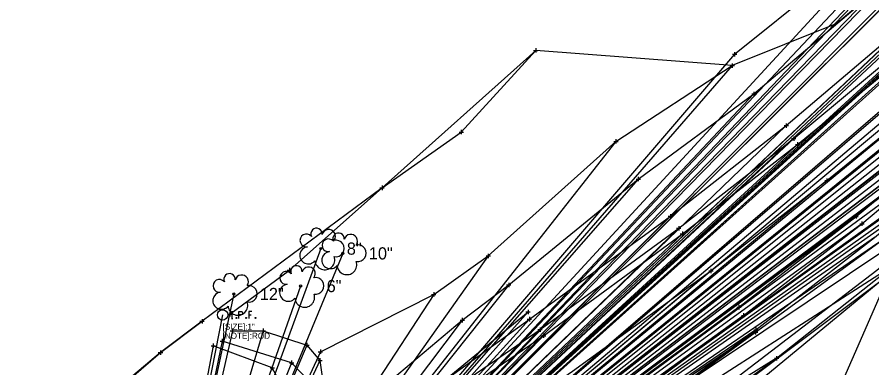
# Model space of a CAD drawing. Extents: x 2048206 to 2051708, y 354200 to 357644.
# Drawn here: x 2049529.9 to 2049726.6, y 356439.5 to 356520.1 of the extents above; entities that cross this region are included whole.
import ezdxf

# ---------------------------------------------------------------- set-up
doc = ezdxf.new("R2010")
doc.units = 0
for name, color, linetype in [('HY_X_Water_Edge', 7, 'Continuous'), ('PM_X_CL_Double_Solid', 7, 'Continuous'), ('PM_X_Edge_Line', 7, 'Continuous'), ('RD_X_GR_Lt', 7, 'Continuous'), ('RD_X_GR_Rt', 7, 'Continuous'), ('RW_X_CL_1000_Cardinal_Points', 7, 'Continuous'), ('RW_X_CL_1000_Curve_Data', 7, 'Continuous'), ('RW_X_CL_1000_Distances', 7, 'Continuous'), ('RW_X_CL_1000_Stations', 7, 'Continuous'), ('RW_X_CL_100_Bearings', 7, 'Continuous'), ('RW_X_CL_100_Distances', 7, 'Continuous'), ('RW_X_CL_500_Stations', 7, 'Continuous'), ('SC_Scratch1', 7, 'Continuous'), ('SV_X_Mon_Cells_Found_Text', 7, 'Continuous'), ('SV_X_Terrain_Boundary', 7, 'Continuous'), ('UT_X_Cable_TV', 7, 'Continuous'), ('UT_X_Telecom', 7, 'Continuous'), ('VG_X_Text', 7, 'Continuous'), ('VG_X_Tree_Line_Rt', 7, 'Continuous')]:
    doc.layers.add(name, color=color, linetype=linetype)

msp = doc.modelspace()

# ---------------------------------------------------------------- linework, layer by layer
at = {"layer": 'HY_X_Water_Edge'}
for points in [[(2049599.68, 356443.17), (2049625.75, 356456.37), (2049638.32, 356465.2), (2049667.68, 356491.55), (2049694.48, 356508.98)], [(2049579.41, 356447.98), (2049586.53, 356447.98), (2049596.56, 356444.7), (2049599.58, 356441.17), (2049601.05, 356430.45), (2049601.6, 356418.96)], [(2049598.72, 356417.71), (2049595.35, 356421.56), (2049594.87, 356427.98), (2049588.58, 356439.46), (2049575.02, 356444.56)]]:
    msp.add_lwpolyline(points, dxfattribs=at)
at = {"layer": 'PM_X_CL_Double_Solid'}
msp.add_lwpolyline([(2049375.85, 356259.2), (2049407.64, 356278.84), (2049446.04, 356302.47), (2049477.81, 356322.2), (2049514.36, 356345.05), (2049555.57, 356371.24), (2049580.57, 356387.08), (2049597.36, 356397.99), (2049622.58, 356414.43), (2049657.71, 356438.71), (2049689.55, 356461.77), (2049716.26, 356482.53), (2049748.26, 356508.44), (2049787.5, 356543.51), (2049807.89, 356562.69), (2049832.63, 356587.13)], dxfattribs=at)
at = {"layer": 'PM_X_Edge_Line'}
for points in [[(2049370.29, 356268.21), (2049401.1, 356287.18), (2049440.53, 356311.34), (2049471.49, 356330.83), (2049508.99, 356354.34), (2049549.13, 356379.71), (2049574.88, 356396.03), (2049597.51, 356410.76), (2049600.43, 356412.78), (2049602.51, 356414.08), (2049606.07, 356416.36), (2049609.95, 356418.83), (2049616.41, 356423.19), (2049651.04, 356446.85), (2049683, 356470.3), (2049709.5, 356490.86), (2049741.12, 356516.75), (2049780.37, 356551.36), (2049801.22, 356570.77), (2049825.54, 356594.9)], [(2049381.31, 356250.14), (2049413.48, 356270.07), (2049450.91, 356293.28), (2049483.11, 356313.23), (2049520.27, 356336.44), (2049560.54, 356361.97), (2049585.44, 356377.69), (2049604.83, 356390.29), (2049628.89, 356406.09), (2049663.97, 356430.06), (2049696.02, 356453.42), (2049722.97, 356474.28), (2049754.43, 356500.26), (2049794.54, 356535.57), (2049814.95, 356554.55), (2049840.5, 356579.69)]]:
    msp.add_lwpolyline(points, dxfattribs=at)
at = {"layer": 'RD_X_GR_Lt'}
msp.add_lwpolyline([(2049366.77, 356272.94), (2049397.1, 356292.33), (2049436.39, 356315.64), (2049468.85, 356335.46), (2049506.36, 356358.42), (2049546.62, 356383.24), (2049572.79, 356399.73), (2049597.57, 356415.65), (2049605.8, 356420.98), (2049614.6, 356426.92), (2049627.17, 356435.72), (2049647.48, 356452.34)], dxfattribs=at)
at = {"layer": 'RD_X_GR_Rt'}
msp.add_lwpolyline([(2049564.55, 356352.93), (2049589.5, 356371.59), (2049618.71, 356390.8), (2049633.04, 356400.3), (2049668.46, 356424.71), (2049699.93, 356448.21), (2049727.18, 356469.44), (2049758.19, 356495.07), (2049799.24, 356531.67), (2049818.56, 356549.77), (2049844.67, 356575.35)], dxfattribs=at)
at = {"layer": 'RW_X_CL_1000_Cardinal_Points'}
for p in [(2049967.48, 356704.03), (2049967.48, 356704.03), (2049887.53, 356618.37), (2049808.42, 356609.48), (2049813.35, 356606.55), (2049820.56, 356599.28), (2049794.64, 356598.37), (2049825.1, 356595.26), (2049825.54, 356594.9), (2049787.92, 356592.43), (2049832.63, 356587.13), (2049832.63, 356587.13), (2049791.16, 356584.29), (2049840.5, 356579.69), (2049841.77, 356578.41), (2049796.57, 356575.48), (2049844.65, 356575.39), (2049844.67, 356575.35), (2049799.72, 356572.07), (2049801.22, 356570.77), (2049762.44, 356568.63), (2049851.09, 356567.09), (2049768.52, 356562.93), (2049807.89, 356562.69), (2049807.89, 356562.69), (2049776.5, 356555.74), (2049814.95, 356554.55), (2049816.11, 356553.32), (2049779.27, 356552.86), (2049780.37, 356551.36), (2049839.38, 356550.87), (2049839.38, 356550.87), (2049818.68, 356550.01), (2049818.56, 356549.77), (2049787.5, 356543.51), (2049787.5, 356543.51), (2049734.41, 356543.24), (2049824.29, 356542.01), (2049794.54, 356535.57), (2049795.79, 356534.44), (2049799.24, 356531.67), (2049799.22, 356531.65), (2049732.64, 356530.57), (2049806, 356525.86), (2049738.23, 356521.78), (2049740.27, 356518.46), (2049741.12, 356516.75), (2049695.02, 356511.58), (2049694.48, 356508.98), (2049748.26, 356508.44), (2049748.26, 356508.44), (2049699.45, 356502.46), (2049754.43, 356500.26), (2049755.38, 356498.64), (2049706.89, 356495.18), (2049758.22, 356495.14), (2049758.19, 356495.07), (2049708.61, 356492.19), (2049667.68, 356491.55), (2049709.5, 356490.86), (2049762.94, 356488.87), (2049672.84, 356482.87), (2049716.26, 356482.53), (2049716.26, 356482.53), (2049680.23, 356474.31), (2049722.97, 356474.28), (2049724.33, 356472.6), (2049682.16, 356471.57), (2049683, 356470.3), (2049727.18, 356469.44), (2049728.19, 356468.27), (2049599.76, 356466.89), (2049604.84, 356465.79), (2049638.32, 356465.2), (2049731.49, 356462.96), (2049689.55, 356461.77), (2049689.55, 356461.77), (2049643.04, 356458.54), (2049595.12, 356458.28), (2049579.74, 356456.45), (2049625.75, 356456.37), (2049696.02, 356453.42), (2049647.48, 356452.34), (2049577.16, 356451.64), (2049697.09, 356451.51), (2049647.79, 356450.66), (2049632.33, 356450.43), (2049650.25, 356448.26), (2049699.93, 356448.21), (2049579.41, 356447.98), (2049586.53, 356447.98), (2049699.83, 356447.65), (2049651.04, 356446.85), (2049577.07, 356445.64), (2049596.56, 356444.7), (2049575.02, 356444.56), (2049599.68, 356443.17), (2049704.68, 356441.67), (2049599.58, 356441.17), (2049593.03, 356440.64)]:
    msp.add_line(p, (2049557.32, 356351.32), dxfattribs=at)
at = {"layer": 'RW_X_CL_1000_Curve_Data'}
for points in [[(2049602.84, 356420.27), (2049602.85, 356421.74), (2049603.97, 356423.3), (2049606.47, 356427.37), (2049611.92, 356433.26), (2049632.33, 356450.43), (2049643.04, 356458.54), (2049672.84, 356482.87), (2049699.45, 356502.46), (2049732.64, 356530.57), (2049768.52, 356562.93), (2049791.16, 356584.29), (2049813.35, 356606.55)], [(2049615.27, 356386.49), (2049616.83, 356385.45), (2049617.67, 356384.58), (2049620.08, 356384.5), (2049625.22, 356386.94), (2049636.96, 356394.29), (2049673.48, 356418.94), (2049704.68, 356441.67), (2049731.49, 356462.96), (2049762.94, 356488.87), (2049806, 356525.86), (2049824.29, 356542.01), (2049851.09, 356567.09)], [(2049578.81, 356451.78), (2049592.53, 356461.93), (2049613.86, 356480.86), (2049632.11, 356493.67), (2049649.25, 356512.45)], [(2049501.84, 356388.73), (2049519.66, 356406.66), (2049543.38, 356426.24), (2049562.87, 356442.98), (2049572.43, 356450.17)], [(2049600.03, 356418.41), (2049597.6, 356424.72), (2049598.32, 356435.15), (2049593.03, 356440.64), (2049577.07, 356445.64)]]:
    msp.add_lwpolyline(points, dxfattribs=at)
at = {"layer": 'RW_X_CL_1000_Distances'}
msp.add_lwpolyline([(2049375.85, 356259.2), (2049407.64, 356278.84), (2049446.04, 356302.47), (2049477.81, 356322.2), (2049514.36, 356345.05), (2049555.57, 356371.24), (2049580.57, 356387.08), (2049597.36, 356397.99), (2049622.58, 356414.43), (2049657.71, 356438.71), (2049689.55, 356461.77), (2049716.26, 356482.53), (2049748.26, 356508.44), (2049787.5, 356543.51), (2049807.89, 356562.69), (2049832.63, 356587.13)], dxfattribs=at)
at = {"layer": 'RW_X_CL_1000_Stations'}
for points in [[(2049604.44, 356419.29), (2049608.51, 356422.62), (2049614.59, 356426.91), (2049627.66, 356436.13), (2049647.79, 356450.66), (2049680.23, 356474.31), (2049706.89, 356495.18), (2049738.23, 356521.78), (2049776.5, 356555.74), (2049796.57, 356575.48), (2049820.56, 356599.28)], [(2049384.67, 356245.45), (2049416.71, 356265.21), (2049453.29, 356287.83), (2049486.41, 356308.51), (2049523.32, 356331.21), (2049564.11, 356356.23), (2049589.23, 356371.82), (2049607.23, 356384.34), (2049608.79, 356386.35), (2049611.22, 356388.3), (2049614.01, 356389.53), (2049617.63, 356390.26), (2049633.05, 356400.32), (2049668.45, 356424.77), (2049699.83, 356447.65), (2049728.19, 356468.27), (2049758.22, 356495.14), (2049799.22, 356531.65), (2049818.68, 356550.01), (2049844.65, 356575.39)]]:
    msp.add_lwpolyline(points, dxfattribs=at)
at = {"layer": 'RW_X_CL_100_Bearings'}
for points in [[(2049579.18, 356452.44), (2049579.53, 356452.44)], [(2049579.35, 356450.84), (2049579.35, 356452.44)], [(2049580.92, 356450.84), (2049580.92, 356452.44), (2049581.45, 356452.44), (2049581.5, 356452.42), (2049581.58, 356452.4), (2049581.61, 356452.37), (2049581.64, 356452.35), (2049581.69, 356452.28), (2049581.72, 356452.22), (2049581.74, 356452.12), (2049581.74, 356451.97), (2049581.73, 356451.92), (2049581.71, 356451.84), (2049581.67, 356451.75), (2049581.62, 356451.72), (2049581.59, 356451.69), (2049581.53, 356451.67), (2049581.45, 356451.65), (2049580.92, 356451.65)], [(2049583.93, 356452.44), (2049583.17, 356452.44), (2049583.17, 356450.84)], [(2049583.17, 356451.65), (2049583.71, 356451.65)], [(2049579.18, 356450.84), (2049579.53, 356450.84)], [(2049580.31, 356451.05), (2049580.37, 356451.05), (2049580.4, 356451.02), (2049580.43, 356450.97), (2049580.43, 356450.91), (2049580.4, 356450.86), (2049580.37, 356450.84), (2049580.31, 356450.84), (2049580.28, 356450.86), (2049580.25, 356450.91), (2049580.25, 356450.97), (2049580.28, 356451.02), (2049580.31, 356451.05)], [(2049582.56, 356451.05), (2049582.62, 356451.05), (2049582.65, 356451.02), (2049582.68, 356450.97), (2049582.68, 356450.91), (2049582.65, 356450.86), (2049582.62, 356450.84), (2049582.56, 356450.84), (2049582.53, 356450.86), (2049582.49, 356450.91), (2049582.49, 356450.97), (2049582.53, 356451.02), (2049582.56, 356451.05)], [(2049584.71, 356451.05), (2049584.76, 356451.05), (2049584.8, 356451.02), (2049584.83, 356450.97), (2049584.83, 356450.91), (2049584.8, 356450.86), (2049584.76, 356450.84), (2049584.71, 356450.84), (2049584.68, 356450.86), (2049584.64, 356450.91), (2049584.64, 356450.97), (2049584.68, 356451.02), (2049584.71, 356451.05)]]:
    msp.add_lwpolyline(points, dxfattribs=at)
msp.add_circle((2049577.16, 356451.64), 1.2, dxfattribs=at)
at = {"layer": 'RW_X_CL_100_Distances'}
for points in [[(2049369.24, 356269.8), (2049399.69, 356288.2), (2049439.67, 356312.64), (2049471.15, 356332.04), (2049508.77, 356355.76), (2049548.41, 356380.39), (2049574.36, 356397.56), (2049598.93, 356414.15), (2049600.34, 356415.6), (2049602.48, 356416.72), (2049605.55, 356417.98), (2049609.34, 356420.32), (2049615.78, 356424.71), (2049650.25, 356448.26), (2049682.16, 356471.57), (2049708.61, 356492.19), (2049740.27, 356518.46), (2049779.27, 356552.86), (2049799.72, 356572.07), (2049825.1, 356595.26)], [(2049382.2, 356248.75), (2049414.46, 356268.53), (2049451.64, 356291.67), (2049484.42, 356311.57), (2049521.46, 356334.72), (2049562.27, 356359.86), (2049586.57, 356375.27), (2049606.37, 356387.97), (2049630.26, 356403.8), (2049665.35, 356428.06), (2049697.09, 356451.51), (2049724.33, 356472.6), (2049755.38, 356498.64), (2049795.79, 356534.44), (2049816.11, 356553.32), (2049841.77, 356578.41)]]:
    msp.add_lwpolyline(points, dxfattribs=at)
at = {"layer": 'RW_X_CL_500_Stations'}
for centre in [(2049599.76, 356466.89), (2049604.84, 356465.79), (2049595.12, 356458.28), (2049579.74, 356456.45)]:
    msp.add_circle(centre, 0.24, dxfattribs=at)
for centre, radius, start, end in [((2049598.78, 356470.26), 1.32, 354.0047, 205.9741), ((2049601.59, 356469.72), 1.55, 323.83, 165.0376), ((2049596.45, 356468.76), 1.47, 39.0625, 279.5412), ((2049603.85, 356469.16), 1.32, 354.0047, 205.9741), ((2049606.66, 356468.62), 1.55, 323.83, 165.0376), ((2049596.91, 356465.34), 1.97, 96.1722, 320.5737), ((2049601.53, 356467.65), 1.47, 39.0625, 279.5412), ((2049603.22, 356466.93), 1.91, 259.1453, 101.4596), ((2049608.3, 356465.83), 1.91, 259.1453, 101.4596), ((2049601.98, 356464.24), 1.97, 96.1722, 320.5737), ((2049600.71, 356464.29), 2.28, 184.9476, 19.4572), ((2049605.78, 356463.18), 2.28, 184.9476, 19.4572), ((2049591.81, 356460.15), 1.47, 39.0625, 279.5412), ((2049594.14, 356461.65), 1.32, 354.0047, 205.9741), ((2049596.95, 356461.11), 1.55, 323.83, 165.0376), ((2049576.43, 356458.31), 1.47, 39.0625, 279.5412), ((2049578.76, 356459.82), 1.32, 354.0047, 205.9741), ((2049581.57, 356459.28), 1.55, 323.83, 165.0376), ((2049598.58, 356458.32), 1.91, 259.1453, 101.4596), ((2049583.2, 356456.49), 1.91, 259.1453, 101.4596), ((2049592.27, 356456.73), 1.97, 96.1722, 320.5737), ((2049576.89, 356454.9), 1.97, 96.1722, 320.5737), ((2049596.07, 356455.68), 2.28, 184.9476, 19.4572), ((2049580.69, 356453.84), 2.28, 184.9476, 19.4572)]:
    msp.add_arc(centre, radius, start, end, dxfattribs=at)
at = {"layer": 'SC_Scratch1'}
for p, q in [((2049648.75, 356512.45), (2049649.75, 356512.45)), ((2049649.25, 356512.95), (2049649.25, 356511.95)), ((2049649.25, 356512.45), (2049649.25, 356512.45)), ((2049694.52, 356511.58), (2049695.52, 356511.58)), ((2049695.02, 356512.08), (2049695.02, 356511.08)), ((2049695.02, 356511.58), (2049695.02, 356511.58)), ((2049693.98, 356508.98), (2049694.98, 356508.98)), ((2049694.48, 356509.48), (2049694.48, 356508.48)), ((2049694.48, 356508.98), (2049694.48, 356508.98)), ((2049699.45, 356502.96), (2049699.45, 356501.96)), ((2049698.95, 356502.46), (2049699.95, 356502.46)), ((2049699.45, 356502.46), (2049699.45, 356502.46)), ((2049706.39, 356495.18), (2049707.39, 356495.18)), ((2049706.89, 356495.68), (2049706.89, 356494.68)), ((2049706.89, 356495.18), (2049706.89, 356495.18)), ((2049631.61, 356493.67), (2049632.61, 356493.67)), ((2049632.11, 356494.17), (2049632.11, 356493.17)), ((2049632.11, 356493.67), (2049632.11, 356493.67)), ((2049667.18, 356491.55), (2049668.18, 356491.55)), ((2049667.68, 356492.05), (2049667.68, 356491.05)), ((2049667.68, 356491.55), (2049667.68, 356491.55)), ((2049708.11, 356492.19), (2049709.11, 356492.19)), ((2049708.61, 356492.69), (2049708.61, 356491.69)), ((2049708.61, 356492.19), (2049708.61, 356492.19)), ((2049709, 356490.86), (2049710, 356490.86)), ((2049709.5, 356491.36), (2049709.5, 356490.36)), ((2049709.5, 356490.86), (2049709.5, 356490.86)), ((2049672.84, 356483.37), (2049672.84, 356482.37)), ((2049716.26, 356483.03), (2049716.26, 356482.03)), ((2049716.26, 356483.03), (2049716.26, 356482.03)), ((2049613.86, 356481.36), (2049613.86, 356480.36)), ((2049672.34, 356482.87), (2049673.34, 356482.87)), ((2049672.84, 356482.87), (2049672.84, 356482.87)), ((2049715.76, 356482.53), (2049716.76, 356482.53)), ((2049715.76, 356482.53), (2049716.76, 356482.53)), ((2049716.26, 356482.53), (2049716.26, 356482.53)), ((2049716.26, 356482.53), (2049716.26, 356482.53)), ((2049613.36, 356480.86), (2049614.36, 356480.86)), ((2049613.86, 356480.86), (2049613.86, 356480.86)), ((2049679.73, 356474.31), (2049680.73, 356474.31)), ((2049680.23, 356474.81), (2049680.23, 356473.81)), ((2049680.23, 356474.31), (2049680.23, 356474.31)), ((2049722.47, 356474.28), (2049723.47, 356474.28)), ((2049722.97, 356474.78), (2049722.97, 356473.78)), ((2049722.97, 356474.28), (2049722.97, 356474.28)), ((2049724.33, 356473.1), (2049724.33, 356472.1)), ((2049681.66, 356471.57), (2049682.66, 356471.57)), ((2049682.16, 356472.07), (2049682.16, 356471.07)), ((2049682.16, 356471.57), (2049682.16, 356471.57)), ((2049723.83, 356472.6), (2049724.83, 356472.6)), ((2049724.33, 356472.6), (2049724.33, 356472.6)), ((2049682.5, 356470.3), (2049683.5, 356470.3)), ((2049683, 356470.8), (2049683, 356469.8)), ((2049683, 356470.3), (2049683, 356470.3)), ((2049638.32, 356465.7), (2049638.32, 356464.7)), ((2049637.82, 356465.2), (2049638.82, 356465.2)), ((2049638.32, 356465.2), (2049638.32, 356465.2)), ((2049592.03, 356461.93), (2049593.03, 356461.93)), ((2049592.53, 356462.43), (2049592.53, 356461.43)), ((2049592.53, 356461.93), (2049592.53, 356461.93)), ((2049689.05, 356461.77), (2049690.05, 356461.77)), ((2049689.05, 356461.77), (2049690.05, 356461.77)), ((2049689.55, 356462.27), (2049689.55, 356461.27)), ((2049689.55, 356462.27), (2049689.55, 356461.27)), ((2049689.55, 356461.77), (2049689.55, 356461.77)), ((2049689.55, 356461.77), (2049689.55, 356461.77)), ((2049642.54, 356458.54), (2049643.54, 356458.54)), ((2049643.04, 356459.04), (2049643.04, 356458.04)), ((2049643.04, 356458.54), (2049643.04, 356458.54)), ((2049625.25, 356456.37), (2049626.25, 356456.37)), ((2049625.75, 356456.87), (2049625.75, 356455.87)), ((2049625.75, 356456.37), (2049625.75, 356456.37)), ((2049695.52, 356453.42), (2049696.52, 356453.42)), ((2049696.02, 356453.92), (2049696.02, 356452.92)), ((2049696.02, 356453.42), (2049696.02, 356453.42)), ((2049578.31, 356451.78), (2049579.31, 356451.78)), ((2049578.81, 356452.28), (2049578.81, 356451.28)), ((2049578.81, 356451.78), (2049578.81, 356451.78)), ((2049646.98, 356452.34), (2049647.98, 356452.34)), ((2049647.48, 356452.84), (2049647.48, 356451.84)), ((2049647.48, 356452.34), (2049647.48, 356452.34)), ((2049696.59, 356451.51), (2049697.59, 356451.51)), ((2049697.09, 356452.01), (2049697.09, 356451.01)), ((2049697.09, 356451.51), (2049697.09, 356451.51)), ((2049571.93, 356450.17), (2049572.93, 356450.17)), ((2049572.43, 356450.67), (2049572.43, 356449.67)), ((2049572.43, 356450.17), (2049572.43, 356450.17)), ((2049631.83, 356450.43), (2049632.83, 356450.43)), ((2049632.33, 356450.93), (2049632.33, 356449.93)), ((2049632.33, 356450.43), (2049632.33, 356450.43)), ((2049647.29, 356450.66), (2049648.29, 356450.66)), ((2049647.79, 356451.16), (2049647.79, 356450.16)), ((2049647.79, 356450.66), (2049647.79, 356450.66)), ((2049578.91, 356447.98), (2049579.91, 356447.98)), ((2049579.41, 356448.48), (2049579.41, 356447.48)), ((2049579.41, 356447.98), (2049579.41, 356447.98)), ((2049586.03, 356447.98), (2049587.03, 356447.98)), ((2049586.53, 356448.48), (2049586.53, 356447.48)), ((2049586.53, 356447.98), (2049586.53, 356447.98)), ((2049649.75, 356448.26), (2049650.75, 356448.26)), ((2049650.25, 356448.76), (2049650.25, 356447.76)), ((2049650.25, 356448.26), (2049650.25, 356448.26)), ((2049699.33, 356447.65), (2049700.33, 356447.65)), ((2049699.43, 356448.21), (2049700.43, 356448.21)), ((2049699.83, 356448.15), (2049699.83, 356447.15)), ((2049699.83, 356447.65), (2049699.83, 356447.65)), ((2049699.93, 356448.71), (2049699.93, 356447.71)), ((2049699.93, 356448.21), (2049699.93, 356448.21)), ((2049576.57, 356445.64), (2049577.57, 356445.64)), ((2049577.07, 356446.14), (2049577.07, 356445.14)), ((2049577.07, 356445.64), (2049577.07, 356445.64)), ((2049650.54, 356446.85), (2049651.54, 356446.85)), ((2049651.04, 356447.35), (2049651.04, 356446.35)), ((2049651.04, 356446.85), (2049651.04, 356446.85)), ((2049574.52, 356444.56), (2049575.52, 356444.56)), ((2049575.02, 356445.06), (2049575.02, 356444.06)), ((2049575.02, 356444.56), (2049575.02, 356444.56)), ((2049596.06, 356444.7), (2049597.06, 356444.7)), ((2049596.56, 356445.2), (2049596.56, 356444.2)), ((2049596.56, 356444.7), (2049596.56, 356444.7)), ((2049599.68, 356443.67), (2049599.68, 356442.67)), ((2049562.37, 356442.98), (2049563.37, 356442.98)), ((2049562.87, 356443.48), (2049562.87, 356442.48)), ((2049562.87, 356442.98), (2049562.87, 356442.98)), ((2049599.18, 356443.17), (2049600.18, 356443.17)), ((2049599.58, 356441.67), (2049599.58, 356440.67)), ((2049599.68, 356443.17), (2049599.68, 356443.17)), ((2049704.18, 356441.67), (2049705.18, 356441.67)), ((2049704.68, 356442.17), (2049704.68, 356441.17)), ((2049704.68, 356441.67), (2049704.68, 356441.67)), ((2049588.58, 356439.96), (2049588.58, 356438.96)), ((2049592.53, 356440.64), (2049593.53, 356440.64)), ((2049593.03, 356441.14), (2049593.03, 356440.14)), ((2049593.03, 356440.64), (2049593.03, 356440.64)), ((2049599.08, 356441.17), (2049600.08, 356441.17)), ((2049599.58, 356441.17), (2049599.58, 356441.17)), ((2049588.08, 356439.46), (2049589.08, 356439.46)), ((2049588.58, 356439.46), (2049588.58, 356439.46))]:
    msp.add_line(p, q, dxfattribs=at)
at = {"layer": 'SV_X_Terrain_Boundary'}
for points in [[(2049732.64, 356530.57), (2049718.52, 356518.61), (2049694.48, 356508.98), (2049649.25, 356512.45), (2049613.86, 356480.86), (2049572.43, 356450.17), (2049562.87, 356442.98), (2049519.66, 356406.66), (2049519.46, 356406.47), (2049501.84, 356388.73), (2049464.67, 356344.58), (2049452.06, 356337.48), (2049430.27, 356325.21), (2049412.85, 356314.54), (2049391.53, 356301.48), (2049381.84, 356295.93), (2049360.15, 356283.5)], [(2049489.23, 356304.28), (2049538.2, 356292.15), (2049539.83, 356293.14), (2049561.2, 356306.12), (2049582.57, 356319.09), (2049603.94, 356332.07), (2049625.31, 356345.05), (2049627.74, 356346.54), (2049649.07, 356359.59), (2049670.39, 356372.64), (2049691.71, 356385.7), (2049713.03, 356398.75), (2049716.17, 356402.59), (2049712.61, 356419.85), (2049731.49, 356462.96), (2049750.78, 356478.85), (2049762.94, 356488.87), (2049781.91, 356505.16), (2049800.87, 356521.45)]]:
    msp.add_lwpolyline(points, dxfattribs=at)
at = {"layer": 'UT_X_Cable_TV'}
msp.add_lwpolyline([(2049173.02, 356101.71), (2049398.29, 356234.18), (2049648.28, 356393.26), (2049839.38, 356550.87), (2049967.48, 356704.03)], dxfattribs=at)
at = {"layer": 'UT_X_Telecom'}
for points in [[(2049850.43, 356569.7), (2049830.16, 356550.49), (2049805.94, 356528.04), (2049766.42, 356494.8), (2049727.75, 356461.86), (2049691.42, 356434.05), (2049649.69, 356403.16), (2049608.1, 356376.9), (2049565.89, 356349.66), (2049558.29, 356353.33), (2049513.15, 356326.07), (2049465.28, 356295.46), (2049465.49, 356295.17), (2049468.31, 356290.92)], [(2049852.66, 356568.7), (2049832.09, 356548.43), (2049807.81, 356526.38), (2049768.27, 356493.06), (2049729.69, 356460.16), (2049693.43, 356433.05), (2049650.82, 356402.18), (2049609.75, 356374.99), (2049566.91, 356348.69), (2049517.39, 356319.13), (2049467.86, 356289.43)]]:
    msp.add_lwpolyline(points, dxfattribs=at)
at = {"layer": 'VG_X_Tree_Line_Rt'}
msp.add_lwpolyline([(2049695.02, 356511.58), (2049734.41, 356543.24), (2049762.44, 356568.63), (2049787.92, 356592.43)], dxfattribs=at)

# ---------------------------------------------------------------- texts
at = {"layer": 'SV_X_Mon_Cells_Found_Text'}
for s, p in [('[SIZE]:1"', (2049577.16, 356448.24)), ('[NOTE]:ROD', (2049577.16, 356446.14))]:
    msp.add_text(s, height=1.4, dxfattribs=at).set_placement(p)
at = {"layer": 'VG_X_Text'}
for s, p in [('8"', (2049605.76, 356465.49)), ('10"', (2049610.84, 356464.39)), ('6"', (2049601.12, 356456.88)), ('12"', (2049585.74, 356455.05))]:
    msp.add_text(s, height=2.8, dxfattribs=at).set_placement(p)

doc.saveas('drawing.dxf')
